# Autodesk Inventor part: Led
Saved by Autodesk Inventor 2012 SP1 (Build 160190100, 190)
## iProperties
Created: 2014-12
Part Number: Led
Material: Default
Document SubType Name: Modeling
Designer: Bruno
Density: 1 g/cm^3
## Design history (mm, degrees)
node "Led1"
node "Led"
node "Base1"
